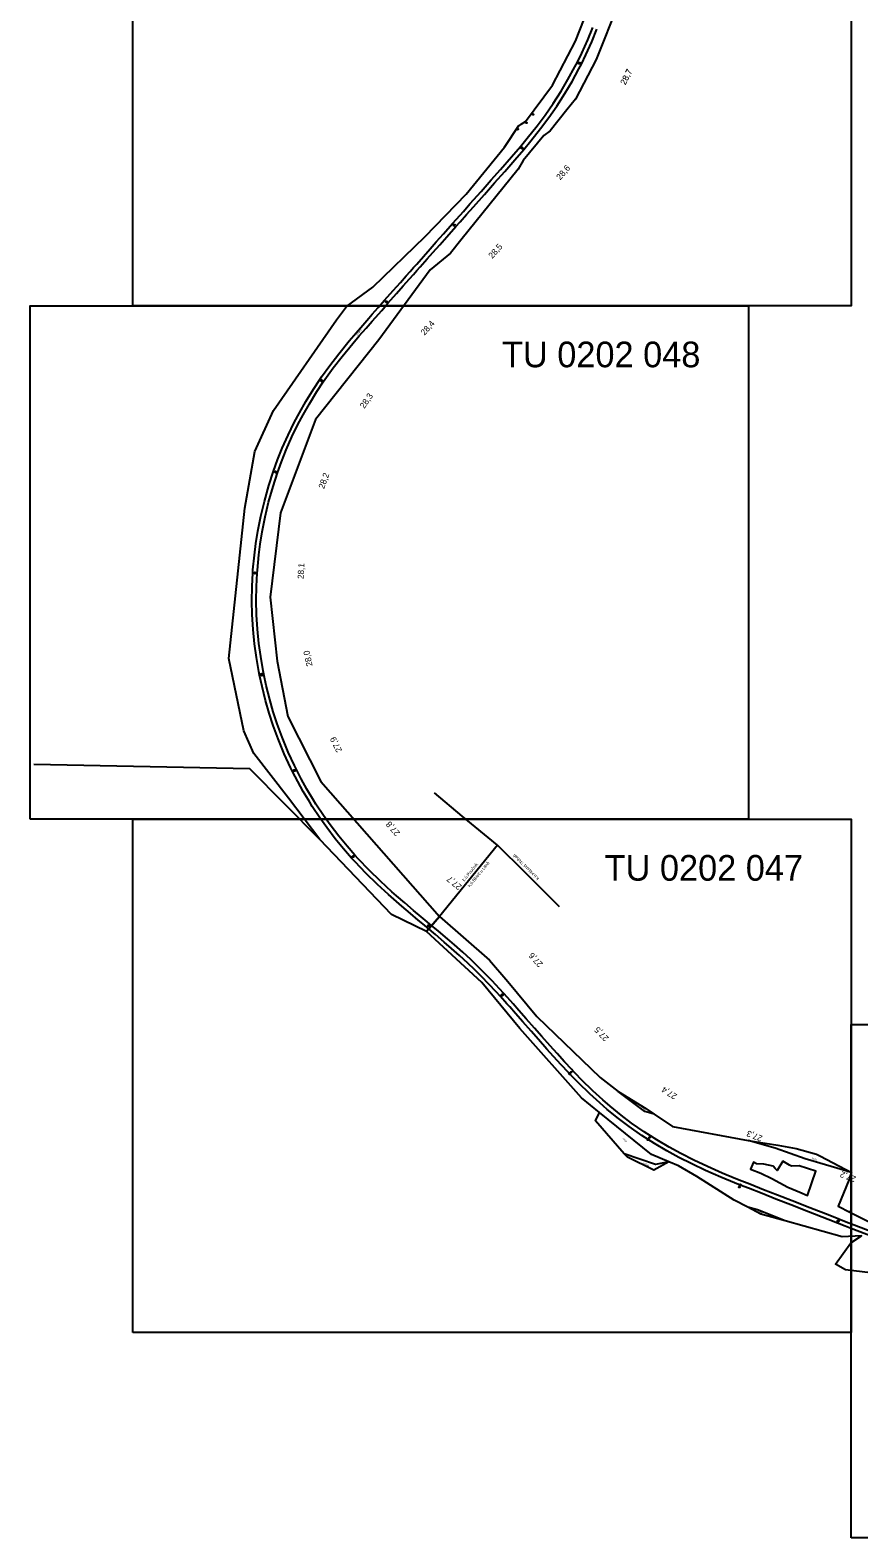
# Model space of a CAD drawing. Extents: x -768800 to -748700, y -1061452 to -1051366.
# Drawn here: x -762600 to -761793, y -1059700 to -1058232 of the extents above; entities that cross this region are included whole.
import ezdxf

# ---------------------------------------------------------------- set-up
doc = ezdxf.new("R2010")
doc.units = 0
for name, color, linetype in [('Vrstva 1', 7, 'Continuous'), ('Vrstva 2', 7, 'Continuous'), ('Vrstva 53', 7, 'Continuous'), ('Vrstva 55', 7, 'Continuous'), ('Vrstva 57', 7, 'Continuous'), ('Vrstva 7', 7, 'Continuous')]:
    doc.layers.add(name, color=color, linetype=linetype)

msp = doc.modelspace()

# ---------------------------------------------------------------- linework, layer by layer
at = {"layer": 'Vrstva 1'}
for points in [[(-762500, -1058500), (-762500, -1058000), (-761800, -1058000), (-761800, -1058500), (-762500, -1058500)], [(-761778.2, -1059407.2), (-761801, -1059398.3), (-761806, -1059396.3), (-761813.6, -1059393.4), (-761822.4, -1059389.9), (-761841.7, -1059382.4), (-761858.9, -1059375.7), (-761873.5, -1059370), (-761886.9, -1059364.7), (-761900.3, -1059359.5), (-761908.2, -1059356.4), (-761913.8, -1059354.1), (-761927, -1059348.6), (-761942.1, -1059342.1), (-761955.2, -1059335.9), (-761968.1, -1059329.5), (-761979.6, -1059323.1), (-761991.7, -1059316), (-761998, -1059312), (-762004.2, -1059308), (-762016.4, -1059299.4), (-762026.9, -1059291.5), (-762037.7, -1059282.7), (-762045, -1059276.5), (-762054.8, -1059267.6), (-762065.8, -1059256.9), (-762071.5, -1059251), (-762074.3, -1059248.1), (-762075.6, -1059246.8), (-762082.6, -1059239.3), (-762090, -1059231.3), (-762096.6, -1059224), (-762104.8, -1059214.7), (-762111.9, -1059206.6), (-762120, -1059197.3), (-762127.1, -1059189.2), (-762132.8, -1059182.7), (-762135.5, -1059179.8), (-762141.8, -1059172.8), (-762146.1, -1059168.1), (-762153.2, -1059160.7), (-762160.4, -1059153.3), (-762167.2, -1059146.6), (-762173.7, -1059140.3), (-762181.8, -1059132.9), (-762189.4, -1059126), (-762196.5, -1059119.9), (-762205.1, -1059112.5), (-762213.2, -1059105.7), (-762215.9, -1059103.4), (-762221.9, -1059098.4), (-762229.3, -1059092.1), (-762237.8, -1059084.9), (-762245.8, -1059077.9), (-762250.8, -1059073.6), (-762261.5, -1059063.7), (-762272.8, -1059052.8), (-762283.5, -1059041.6), (-762286.8, -1059038), (-762294.7, -1059029.1), (-762302.7, -1059019.2), (-762311.1, -1059008.2), (-762317.7, -1058998.9), (-762325.1, -1058987.7), (-762327.6, -1058983.6), (-762333.9, -1058973.1), (-762339.3, -1058963.4), (-762344.3, -1058953.6), (-762346.2, -1058949.8), (-762352.4, -1058936.3), (-762358.4, -1058921.7), (-762363.2, -1058908.7), (-762367, -1058897), (-762370.6, -1058884.5), (-762374.1, -1058870.8), (-762376.5, -1058859.8), (-762377.2, -1058856.2), (-762379.5, -1058842.5), (-762381.3, -1058829.3), (-762382.7, -1058815.4), (-762383.6, -1058800.8), (-762383.9, -1058787.9), (-762383.7, -1058773.5), (-762383.1, -1058760.2), (-762382.9, -1058757.4), (-762381.5, -1058743.1), (-762380.1, -1058731.7), (-762378.2, -1058719.7), (-762375.3, -1058705.1), (-762371.8, -1058690.6), (-762367.5, -1058675.1), (-762363, -1058661.3), (-762358.9, -1058650.1), (-762354.4, -1058638.8), (-762348.7, -1058626), (-762342.7, -1058613.7), (-762337.7, -1058604.3), (-762331.5, -1058593.4), (-762324, -1058581.2), (-762317.9, -1058572), (-762316, -1058569.3), (-762308, -1058558.2), (-762299.2, -1058546.8), (-762289.1, -1058534.3), (-762282.5, -1058526.5), (-762276, -1058518.9), (-762270.1, -1058512.1), (-762266.8, -1058508.4), (-762260.9, -1058501.7), (-762254.7, -1058494.7), (-762246.4, -1058485.3), (-762239.3, -1058477.4), (-762233.6, -1058470.9), (-762229.8, -1058466.6), (-762226.4, -1058462.9), (-762223.4, -1058459.5), (-762216.8, -1058452), (-762210.2, -1058444.6), (-762204.3, -1058437.9), (-762197.2, -1058430), (-762188.5, -1058420.1), (-762184.7, -1058415.8), (-762177.9, -1058408.2), (-762171.5, -1058400.9), (-762160.7, -1058388.8), (-762150.8, -1058377.6), (-762141.8, -1058367.5), (-762131, -1058355.1), (-762122.3, -1058345), (-762115.7, -1058336.9), (-762106.1, -1058324.9), (-762098.2, -1058314.3), (-762090.5, -1058303.2), (-762082.8, -1058291.2), (-762076.1, -1058279.8), (-762069.2, -1058267.3), (-762066.9, -1058262.7), (-762062.6, -1058254.1), (-762056.8, -1058241.2), (-762051.9, -1058229)], [(-761776.8, -1059403.3), (-761799.8, -1059394.4), (-761805, -1059392.4), (-761812.2, -1059389.6), (-761820.8, -1059386.2), (-761840.3, -1059378.6), (-761857.5, -1059371.8), (-761872, -1059366.2), (-761885.4, -1059361), (-761898.7, -1059355.7), (-761906.7, -1059352.5), (-761912.4, -1059350.2), (-761925.8, -1059344.7), (-761940.2, -1059338.4), (-761953.4, -1059332.2), (-761966.2, -1059325.8), (-761977.6, -1059319.6), (-761989.6, -1059312.4), (-761995.7, -1059308.5), (-762001.8, -1059304.5), (-762014, -1059296), (-762024.3, -1059288.2), (-762034.9, -1059279.6), (-762042.2, -1059273.3), (-762051.7, -1059264.7), (-762062.7, -1059253.9), (-762068.6, -1059247.9), (-762071.3, -1059245.1), (-762072.4, -1059243.9), (-762079.5, -1059236.3), (-762086.7, -1059228.4), (-762093.5, -1059220.9), (-762101.6, -1059211.7), (-762108.6, -1059203.7), (-762116.7, -1059194.5), (-762123.8, -1059186.4), (-762129.5, -1059179.9), (-762132.1, -1059177), (-762138.5, -1059169.9), (-762142.8, -1059165.2), (-762150, -1059157.5), (-762157.3, -1059150.1), (-762164.1, -1059143.2), (-762170.8, -1059136.9), (-762178.6, -1059129.6), (-762186.5, -1059122.6), (-762193.5, -1059116.5), (-762202.3, -1059109.2), (-762210.5, -1059102.3), (-762213.1, -1059100.1), (-762219.1, -1059095.1), (-762226.5, -1059089), (-762235, -1059081.7), (-762243.1, -1059074.8), (-762247.7, -1059070.7), (-762258.8, -1059060.6), (-762269.8, -1059049.9), (-762280.5, -1059038.7), (-762283.8, -1059035.1), (-762291.3, -1059026.5), (-762299.4, -1059016.7), (-762307.8, -1059005.6), (-762314.3, -1058996.4), (-762321.6, -1058985.5), (-762324, -1058981.6), (-762330.4, -1058970.8), (-762335.9, -1058960.8), (-762340.5, -1058951.8), (-762342.5, -1058947.8), (-762348.5, -1058934.8), (-762354.5, -1058920.3), (-762359.2, -1058907.3), (-762363.1, -1058895.6), (-762366.6, -1058883.6), (-762370, -1058869.8), (-762372.4, -1058859), (-762373, -1058855.5), (-762375.4, -1058841.8), (-762377.1, -1058829.1), (-762378.5, -1058815.2), (-762379.4, -1058801), (-762379.7, -1058787.2), (-762379.5, -1058773.6), (-762378.8, -1058760.5), (-762378.6, -1058757.6), (-762377.2, -1058742.6), (-762375.9, -1058732.3), (-762374, -1058720.2), (-762371.1, -1058705.6), (-762367.8, -1058691.5), (-762363.4, -1058676), (-762359.1, -1058662.7), (-762355.2, -1058652), (-762350.5, -1058640.4), (-762345, -1058627.8), (-762339.1, -1058615.7), (-762334.1, -1058606.3), (-762328, -1058595.5), (-762320.7, -1058583.7), (-762314.4, -1058574.2), (-762312.8, -1058571.9), (-762304.7, -1058560.6), (-762295.9, -1058549.4), (-762285.7, -1058536.9), (-762279.3, -1058529.5), (-762272.7, -1058521.8), (-762266.8, -1058515.1), (-762263.6, -1058511.4), (-762257.5, -1058504.6), (-762251.4, -1058497.6), (-762243.1, -1058488.2), (-762236.5, -1058480.8), (-762230.4, -1058473.9), (-762226.6, -1058469.6), (-762223.3, -1058465.9), (-762220.1, -1058462.3), (-762213.2, -1058454.5), (-762207.6, -1058448.2), (-762201, -1058440.8), (-762194, -1058432.8), (-762185.2, -1058422.9), (-762181.2, -1058418.4), (-762174.8, -1058411.1), (-762168.1, -1058403.6), (-762157.5, -1058391.7), (-762147.6, -1058380.4), (-762137.7, -1058369.2), (-762127.7, -1058357.9), (-762119.1, -1058347.8), (-762112.3, -1058339.6), (-762102.7, -1058327.6), (-762094.6, -1058316.8), (-762086.8, -1058305.6), (-762079, -1058293.5), (-762072.1, -1058281.8), (-762065.3, -1058269.3), (-762062.9, -1058264.7), (-762058.5, -1058255.8), (-762052.7, -1058242.9), (-762047.8, -1058230.7)], [(-762600, -1059000), (-762600, -1058500), (-761900, -1058500), (-761900, -1059000), (-762600, -1059000)], [(-762500, -1059500), (-762500, -1059000), (-761800, -1059000), (-761800, -1059500), (-762500, -1059500)], [(-761800, -1059700), (-761800, -1059200), (-761100, -1059200), (-761100, -1059700), (-761800, -1059700)]]:
    msp.add_lwpolyline(points, dxfattribs=at)
at = {"layer": 'Vrstva 53'}
for p, q in [((-762110, -1058313.8), (-762109.9, -1058313.8)), ((-762125.1, -1058328.1), (-762125, -1058328.1)), ((-762116.5, -1058321.9), (-762116.4, -1058321.9)), ((-761801.4, -1059382.6), (-761801.5, -1059382.5))]:
    msp.add_line(p, q, dxfattribs=at)
for points in [[(-762026.9, -1058205.6), (-762048.4, -1058260.1), (-762068.6, -1058298.9), (-762077.1, -1058309.2), (-762093.3, -1058329.8), (-762099.6, -1058334.2), (-762119.8, -1058358.5), (-762124.4, -1058367.2), (-762180.5, -1058436.2), (-762190.4, -1058448.7), (-762210.2, -1058465), (-762260.2, -1058533.4), (-762322, -1058610.7), (-762356.1, -1058701.8), (-762366.3, -1058783.9), (-762359.3, -1058846.2), (-762349.1, -1058900), (-762316.7, -1058963.5), (-762201.2, -1059094.8), (-762152.4, -1059137.4), (-762134.6, -1059158.1), (-762106.5, -1059192.2), (-762044.6, -1059251.6), (-762027, -1059265.2), (-762000.2, -1059281.9), (-761991.9, -1059287.5), (-761974.2, -1059299.5), (-761900.6, -1059313.1), (-761871.7, -1059317.7), (-761853.6, -1059320.8), (-761833.9, -1059326.2), (-761830.1, -1059328.4), (-761799.8, -1059344.1), (-761800.3, -1059345.5), (-761802.4, -1059351.6), (-761812.7, -1059377.1), (-761801.3, -1059382.7), (-761783.3, -1059391.9)], [(-761781.3, -1059442), (-761805.8, -1059439.1), (-761815.4, -1059433.5), (-761800.3, -1059412.6), (-761790, -1059405.8), (-761808.8, -1059406.7), (-761864.3, -1059391.3), (-761888.1, -1059384.7), (-761900.8, -1059378.1), (-761914, -1059371.2), (-761950.4, -1059348.1), (-761968.3, -1059337.7), (-761977.7, -1059333.7), (-761992.4, -1059341.8), (-762018.1, -1059329.3), (-762021.2, -1059325.9), (-762049.3, -1059294), (-762045.4, -1059285.6), (-762063, -1059271.5), (-762123, -1059203.9), (-762159.8, -1059159.3), (-762213.7, -1059109.6), (-762247.8, -1059093), (-762317.9, -1059019.9), (-762348.4, -1058979.7), (-762382.2, -1058936), (-762391.9, -1058914.2), (-762406.4, -1058843.7), (-762390.9, -1058697.1), (-762381.2, -1058642), (-762363, -1058602.1), (-762301.5, -1058513.9), (-762291.7, -1058500.7), (-762266.3, -1058482), (-762215.3, -1058432.6), (-762175.1, -1058391.4), (-762137.8, -1058345.7), (-762124, -1058324.5), (-762121.7, -1058323.1), (-762117.4, -1058320.5), (-762091, -1058285.4), (-762068.7, -1058242.3), (-762060.2, -1058221)], [(-761866.8, -1059333), (-761872.3, -1059342.4), (-761874.3, -1059340.3), (-761876, -1059338.1), (-761885.1, -1059336), (-761892.3, -1059335.7), (-761895.4, -1059334.2), (-761898.2, -1059340.8), (-761888.1, -1059344.8), (-761877.3, -1059349.9), (-761861.8, -1059358.5), (-761850.2, -1059363.5), (-761842.6, -1059366.5), (-761834.5, -1059343), (-761850.8, -1059337.6), (-761858.4, -1059338), (-761860.1, -1059336.9), (-761866.8, -1059333)]]:
    msp.add_lwpolyline(points, dxfattribs=at)
for centre in [(-762109.9, -1058313.8), (-762125, -1058328.1), (-762116.5, -1058321.9), (-761801.4, -1059382.6)]:
    msp.add_circle(centre, 0.499, dxfattribs=at)
at = {"layer": 'Vrstva 55'}
for p, q in [((-762144.7, -1059025.5), (-762201.2, -1059094.8)), ((-762213.7, -1059109.6), (-762201.2, -1059094.8)), ((-762201.2, -1059094.8), (-762213.7, -1059109.6))]:
    msp.add_line(p, q, dxfattribs=at)
for points in [[(-762213.7, -1059109.6), (-762247.8, -1059093), (-762317.9, -1059019.9), (-762385.9, -1058951.1), (-762596.5, -1058946.9)], [(-762144.7, -1059025.5), (-762179, -1058997), (-762206.2, -1058974.4)], [(-762144.7, -1059025.5), (-762118.5, -1059051.4), (-762084.7, -1059085.2)], [(-761991.9, -1059287.5), (-762001.3, -1059284.9), (-762027, -1059265.2)], [(-761977.7, -1059333.7), (-761994.6, -1059326.5), (-762045.4, -1059285.6)], [(-761799.8, -1059344.1), (-761844.9, -1059330.9), (-761874.3, -1059320.5), (-761900.6, -1059313.1)], [(-761977.7, -1059333.7), (-761990.6, -1059336.4), (-762021.2, -1059325.9)], [(-761864.3, -1059391.3), (-761891.3, -1059380.6), (-761900.8, -1059378.1)]]:
    msp.add_lwpolyline(points, dxfattribs=at)
at = {"layer": 'Vrstva 7'}
for p, q in [((-762064.9, -1058263.8), (-762064.8, -1058263.7)), ((-762120.8, -1058346.5), (-762120.8, -1058346.4)), ((-762186.9, -1058421.6), (-762186.8, -1058421.5)), ((-762253.1, -1058496.2), (-762253.1, -1058496.2)), ((-762316.1, -1058573.1), (-762316.1, -1058573)), ((-762360.9, -1058662), (-762360.9, -1058661.9)), ((-762381, -1058760.4), (-762381, -1058760.3)), ((-762374.4, -1058859.4), (-762374.4, -1058859.3)), ((-762342.5, -1058952.7), (-762342.5, -1058952.6)), ((-762285.4, -1059036.6), (-762285.4, -1059036.5)), ((-762211.7, -1059103.9), (-762211.8, -1059103.8)), ((-762140.1, -1059171.3), (-762140.1, -1059171.2)), ((-762072.9, -1059246.7), (-762073, -1059246.6)), ((-761996.6, -1059310.3), (-761996.7, -1059310.2)), ((-761909.1, -1059358.4), (-761909.2, -1059358.4)), ((-761812.8, -1059391.4), (-761812.9, -1059391.4))]:
    msp.add_line(p, q, dxfattribs=at)
for centre, radius in [((-762064.9, -1058263.8), 0.75), ((-762064.9, -1058263.8), 0.5), ((-762120.8, -1058346.4), 0.75), ((-762120.8, -1058346.4), 0.5), ((-762186.8, -1058421.6), 0.75), ((-762186.8, -1058421.6), 0.5), ((-762253.1, -1058496.2), 0.75), ((-762253.1, -1058496.2), 0.5), ((-762316.1, -1058573), 0.75), ((-762316.1, -1058573), 0.5), ((-762360.9, -1058662), 0.75), ((-762360.9, -1058662), 0.5), ((-762381, -1058760.4), 0.75), ((-762381, -1058760.4), 0.5), ((-762374.4, -1058859.4), 1.25), ((-762374.4, -1058859.4), 0.752), ((-762374.4, -1058859.4), 0.5), ((-762342.5, -1058952.7), 0.75), ((-762342.5, -1058952.7), 0.5), ((-762285.4, -1059036.5), 0.75), ((-762285.4, -1059036.5), 0.5), ((-762211.7, -1059103.9), 0.75), ((-762211.7, -1059103.9), 0.5), ((-762140.1, -1059171.3), 0.75), ((-762140.1, -1059171.3), 0.5), ((-762074.4, -1059248), 0.75), ((-762072.9, -1059246.6), 0.5), ((-761997.9, -1059312.1), 0.75), ((-761996.7, -1059310.2), 0.5), ((-761908.3, -1059356.3), 0.75), ((-761909.1, -1059358.4), 0.5), ((-761812.8, -1059391.4), 0.75), ((-761812.8, -1059391.4), 0.5)]:
    msp.add_circle(centre, radius, dxfattribs=at)

# ---------------------------------------------------------------- texts
at = {"layer": 'Vrstva 2'}
for s, p in [('TU 0202 048', (-762140.3, -1058560)), ('TU 0202 047', (-762040.3, -1059060))]:
    msp.add_text(s, height=25, dxfattribs=at).set_placement(p)
at = {"layer": 'Vrstva 55'}
for s, rotation, p in [('k.ú.Hlásná Třebaň', 134.9238, (-762103.9, -1059057.6)), ('k.ú.Poučník', 50.7994, (-762177.1, -1059060.9)), ('k.ú.Běleč u Litně', 50.7994, (-762171.6, -1059066.6))]:
    msp.add_text(s, height=3, rotation=rotation, dxfattribs=at).set_placement(p)
at = {"layer": 'Vrstva 57'}
for s, rotation, p in [('1478/18', 53.5529, (-762281.2, -1058529.3)), ('357/4', 142.6937, (-762000.7, -1059283.2)), ('360/2', 143.112, (-762018.4, -1059313.5)), ('363/14', 153.6543, (-761996.9, -1059337)), ('357/5', 163.7557, (-761833.1, -1059331.1)), ('363/17', 156.5575, (-761886.3, -1059383.3))]:
    msp.add_text(s, height=1.5, rotation=rotation, dxfattribs=at).set_placement(p)
at = {"layer": 'Vrstva 7'}
for s, rotation, p in [('28,7', 64.1407, (-762020.1, -1058285.5)), ('28,7', 62.8017, (-762020.1, -1058285.5)), ('28,6', 49.6906, (-762083.5, -1058378.1)), ('28,6', 49.497, (-762083.5, -1058378.1)), ('28,5', 48.4538, (-762149.7, -1058454.6)), ('28,5', 48.4949, (-762149.7, -1058454.6)), ('28,4', 48.4645, (-762215.8, -1058529.4)), ('28,3', 55.5471, (-762274.4, -1058600.7)), ('28,2', 70.0225, (-762313.7, -1058678.8)), ('28,1', 87.2062, (-762333.5, -1058766.4)), ('28,0', 102.2307, (-762324.8, -1058850.6)), ('27,9', 116.2172, (-762295.9, -1058933.2)), ('27,8', 131.1927, (-762239.2, -1059013.3)), ('27,7', 140.1263, (-762179, -1059065)), ('27,6', 132.4466, (-762100, -1059140.9)), ('27,5', 133.728, (-762035.8, -1059213)), ('27,4', 147.7646, (-761969.2, -1059268.5)), ('27,3', 158.3332, (-761886, -1059308.8)), ('27,2', 158.6355, (-761794.9, -1059348.4))]:
    msp.add_text(s, height=6, rotation=rotation, dxfattribs=at).set_placement(p)

doc.saveas('drawing.dxf')
